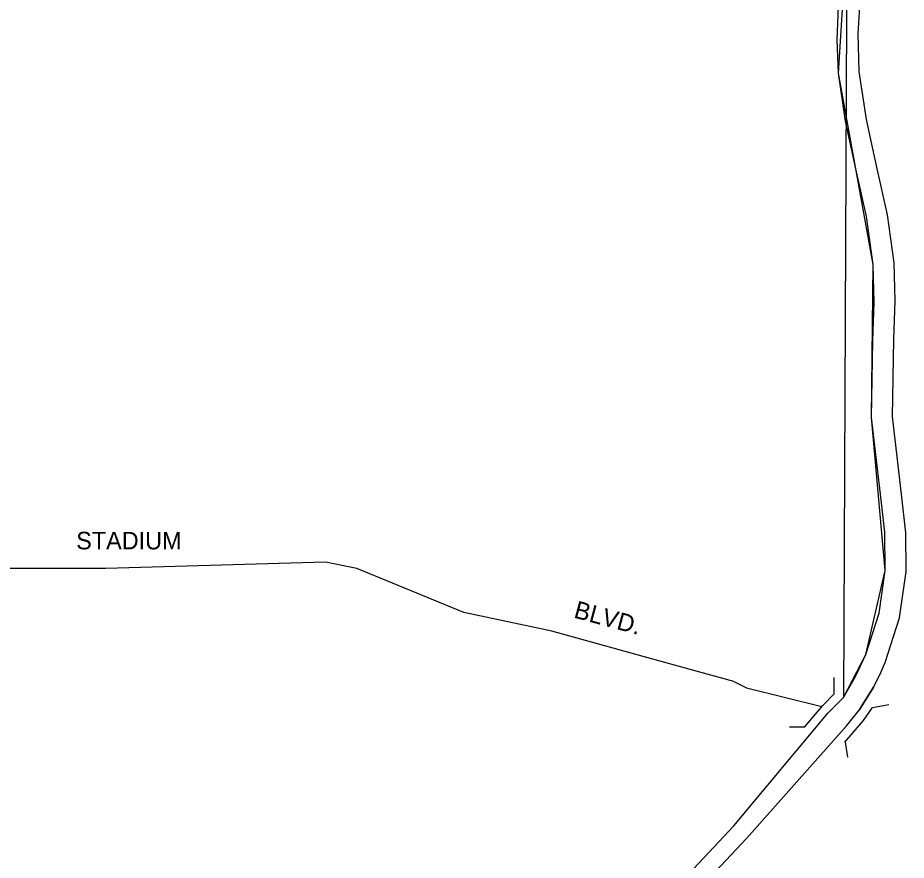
# Model space of a CAD drawing. Extents: x 5.01 to 9.58, y 0.27 to 3.39.
# Drawn here: x 8.037 to 8.588, y 1.858 to 2.381 of the extents above; entities that cross this region are included whole.
import ezdxf

# ---------------------------------------------------------------- set-up
doc = ezdxf.new("R2010")
doc.units = 0
doc.layers.add('MO_001_NOSHOW', color=7, linetype='Continuous')
doc.layers.add('MO_001_VIEW_PV', color=7, linetype='Continuous')

msp = doc.modelspace()

# ---------------------------------------------------------------- linework, layer by layer
at = {"layer": 'MO_001_NOSHOW'}
for points in [[(8.54894, 1.95919), (8.56284, 1.986), (8.57493, 2.03815), (8.56648, 2.1329), (8.56743, 2.22799), (8.54584, 2.34659), (8.55114, 2.42918)], [(8.55872, 1.95137), (8.56771, 1.96561)]]:
    msp.add_lwpolyline(points, close=True, dxfattribs=at)
at = {"layer": 'MO_001_VIEW_PV'}
for p, q in [((8.43809, 1.98089), (8.36795, 2.00031)), ((8.48099, 1.96915), (8.43809, 1.98089)), ((8.54332, 1.96147), (8.54332, 1.97161)), ((8.56709, 1.95306), (8.57724, 1.95494)), ((8.52491, 1.94074), (8.5155, 1.94074)), ((8.54999, 1.93146), (8.55158, 1.92219))]:
    msp.add_line(p, q, dxfattribs=at)
for points in [[(8.54894, 1.95919), (8.55647, 1.97227), (8.56284, 1.986), (8.57107, 2.01162), (8.57493, 2.03815), (8.57461, 2.06182), (8.57202, 2.08547), (8.56648, 2.1329), (8.56723, 2.18057), (8.56807, 2.20435), (8.56743, 2.22799), (8.56325, 2.25771), (8.55677, 2.28724), (8.55022, 2.3168), (8.54584, 2.34659), (8.54506, 2.36724), (8.54596, 2.38795), (8.55114, 2.42918)], [(8.56771, 1.96561), (8.57148, 1.97323), (8.57491, 1.98103), (8.58379, 2.00873), (8.58796, 2.03742), (8.58765, 2.06144), (8.58506, 2.08546), (8.5795, 2.1336), (8.58023, 2.18142), (8.58108, 2.20528), (8.58044, 2.22901), (8.57625, 2.25873), (8.56976, 2.2883), (8.56321, 2.31789), (8.55884, 2.3477), (8.55815, 2.37117), (8.55964, 2.39471)], [(8.22762, 2.04327), (8.09118, 2.03937), (8.0288, 2.03937)], [(8.36793, 2.00038), (8.31338, 2.01207), (8.2471, 2.03937), (8.22762, 2.04327)], [(8.48098, 1.96921), (8.48878, 1.96531), (8.53555, 1.95361), (8.53559, 1.95356)], [(8.55872, 1.95137), (8.56321, 1.95849), (8.56771, 1.96561)], [(8.15744, 1.53262), (8.16524, 1.54041), (8.2432, 1.62617), (8.48098, 1.87955), (8.53945, 1.9497), (8.54894, 1.95919)], [(8.52493, 1.94078), (8.53627, 1.95437), (8.54331, 1.96142)], [(8.54994, 1.93145), (8.56136, 1.94496), (8.56707, 1.95311)], [(8.16913, 1.52872), (8.17303, 1.53262), (8.251, 1.61838), (8.48878, 1.87176), (8.55114, 1.94191), (8.55872, 1.95137)]]:
    msp.add_lwpolyline(points, dxfattribs=at)

# ---------------------------------------------------------------- texts
msp.add_text('STADIUM', height=0.01087, dxfattribs=at).set_placement((8.07286, 2.05116))
msp.add_text('BLVD.', height=0.01087, rotation=345, dxfattribs=at).set_placement((8.38113, 2.00893))

doc.saveas('drawing.dxf')
